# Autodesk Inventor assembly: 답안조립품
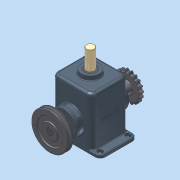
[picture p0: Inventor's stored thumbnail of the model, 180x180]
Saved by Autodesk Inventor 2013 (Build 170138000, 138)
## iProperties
Created: 2015-03
Part Number: 답안조립품
Document SubType Name: Assembly
Designer: Administrator
Mass: 8578.97 g
Surface Area: 4386.44 cm^2
Volume: 1982.5 cm^3
Density: 4.32735 g/cm^3
Author: Administrator
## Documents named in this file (15)
- C:\Users\Administrator\Desktop\350306V1001\답안조립품.iam
- C:\Users\Administrator\Desktop\350306V1001\본체.ipt
- C:\Users\Administrator\Desktop\350306V1001\M4x0.5.ipt
- C:\Users\Administrator\Desktop\350306V1001\V-벨트풀리.ipt
- C:\Users\Administrator\Desktop\350306V1001\가변스프링.ipt
- C:\Users\Administrator\Desktop\350306V1001\멈춤나사 M5x0.5.ipt
- C:\Users\Administrator\Desktop\350306V1001\멈춤링.ipt
- C:\Users\Administrator\Desktop\350306V1001\베어링 6205.ipt
- C:\Users\Administrator\Desktop\350306V1001\부시.ipt
- C:\Users\Administrator\Desktop\350306V1001\슬라이드.ipt
- C:\Users\Administrator\Desktop\350306V1001\오일실.ipt
- C:\Users\Administrator\Desktop\350306V1001\체인 스프로킷.ipt
- C:\Users\Administrator\Desktop\350306V1001\커버.ipt
- C:\Users\Administrator\Desktop\350306V1001\키 8x8.ipt
- C:\Users\Administrator\Desktop\350306V1001\편심축.ipt
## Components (9 placed, 4 different names)
1. V-벨트풀리:1 — 플러쉬:3
2. 가변스프링:1
3. 5-체인 스프로킷:1 — 플러쉬:2
4. M4x0.5:1
5. M4x0.5:3
6. M4x0.5:4
7. M4x0.5:2
8. M4x0.5:5
9. M4x0.5:6
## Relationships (2: Flush 2)
- 플러쉬:2 [Flush]: 5-체인 스프로킷:1
- 플러쉬:3 [Flush]: V-벨트풀리:1
